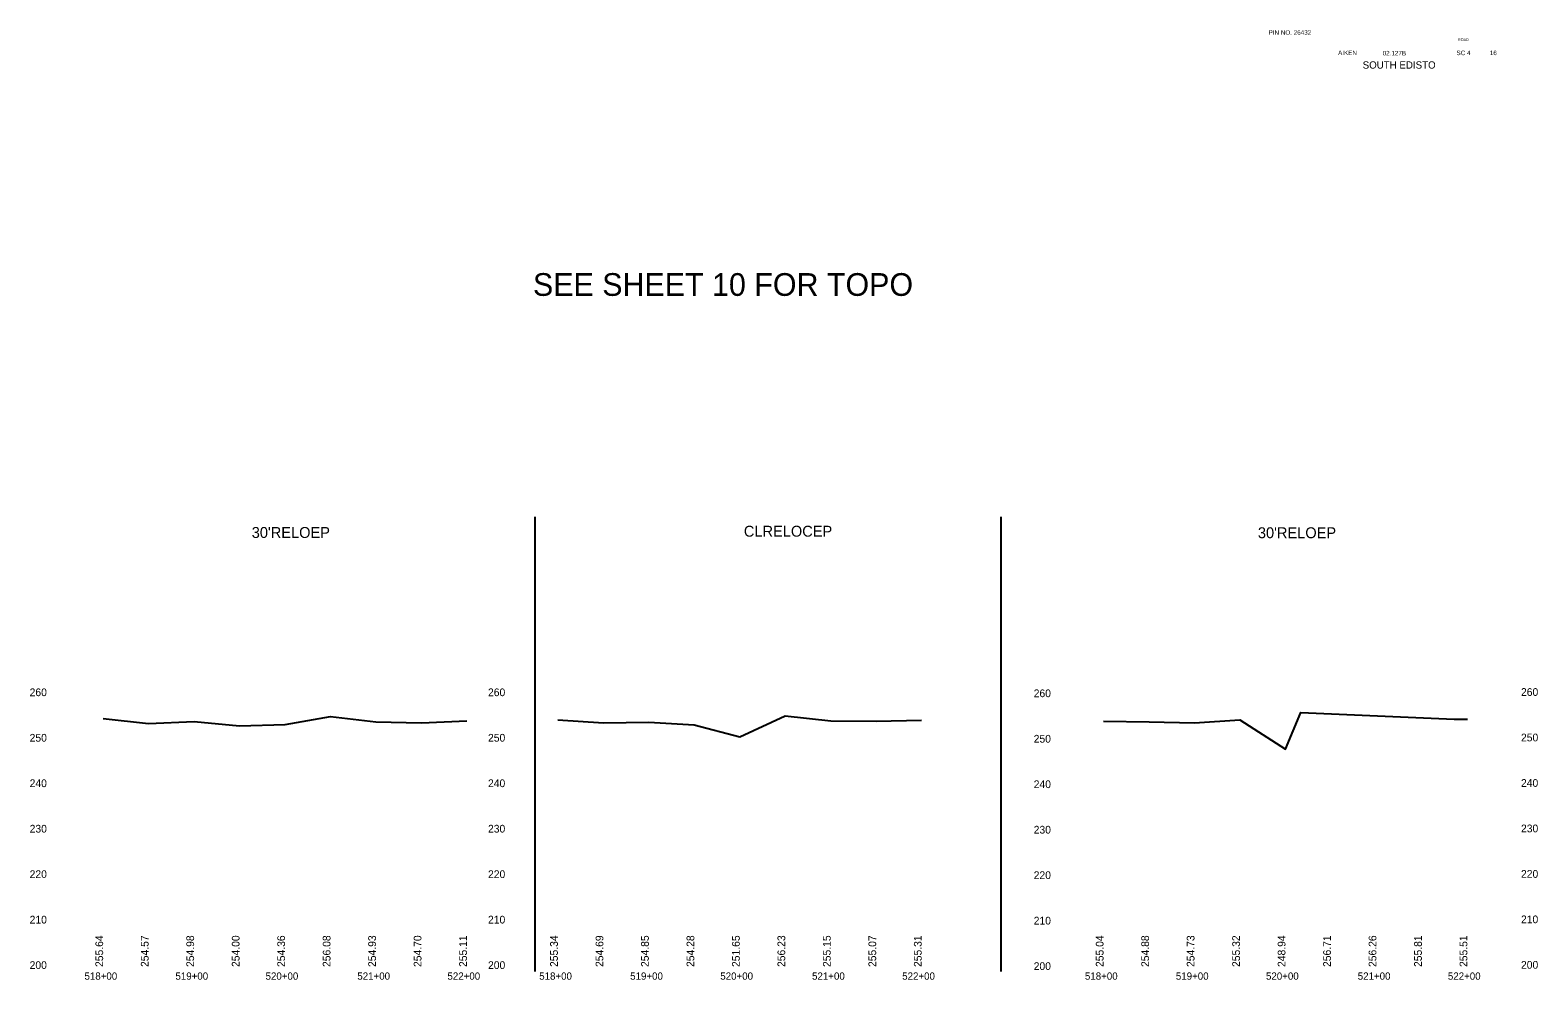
# Model space of a CAD drawing. Extents: x 49241 to 62599, y 49216 to 56011.
# Drawn here: x 50163 to 51821, y 54966 to 56011 of the extents above; entities that cross this region are included whole.
import ezdxf

# ---------------------------------------------------------------- set-up
doc = ezdxf.new("R2010")
doc.units = 0
for name, color, linetype in [('Level 1', 7, 'Continuous'), ('Level 25', 7, 'Continuous'), ('Level 40', 7, 'Continuous'), ('Level 42', 7, 'Continuous'), ('Level 43', 7, 'Continuous')]:
    doc.layers.add(name, color=color, linetype=linetype)

msp = doc.modelspace()

# ---------------------------------------------------------------- linework, layer by layer
at = {"layer": 'Level 1'}
for p, q in [((50718.5, 54975.3), (50718.5, 55475.3)), ((51231.1, 54975.3), (51231.1, 55475.3))]:
    msp.add_line(p, q, dxfattribs=at)
at = {"layer": 'Level 40'}
for points in [[(50243.5, 55253.5), (50293.5, 55248.1), (50343.5, 55250.2), (50393.5, 55245.3), (50443.5, 55247.1), (50493.5, 55255.6), (50543.5, 55249.9), (50593.5, 55248.8), (50643.5, 55250.8)], [(50743.5, 55252), (50793.5, 55248.7), (50843.5, 55249.5), (50893.5, 55246.7), (50943.5, 55233.5), (50993.5, 55256.4), (51043.5, 55251), (51093.5, 55250.6), (51143.5, 55251.8)], [(51343.5, 55250.5), (51393.5, 55249.7), (51443.5, 55248.9), (51493.5, 55251.9), (51543.5, 55220), (51560.5, 55260.3), (51729.2, 55252.7), (51743.5, 55252.8)]]:
    msp.add_lwpolyline(points, dxfattribs=at)

# ---------------------------------------------------------------- texts
at = {"layer": 'Level 1'}
for s, height, p in [('PIN NO. 26432', 5, (51525, 56005.4)), ('ROAD', 3, (51733.2, 55998.5)), ('AIKEN', 5, (51601.4, 55983.1)), ('02.127B', 5, (51650.4, 55982.7)), ('SC 4', 5, (51731.6, 55983)), ('16', 5, (51768.2, 55983)), ('SOUTH EDISTO', 8, (51628.4, 55968.2))]:
    msp.add_text(s, height=height, dxfattribs=at).set_placement(p)
at = {"layer": 'Level 25'}
msp.add_text('SEE SHEET 10 FOR TOPO', height=25, dxfattribs=at).set_placement((50716.1, 55718.3))
at = {"layer": 'Level 42'}
for s, height, p in [('260', 8.5, (50162.7, 55278.1)), ('260', 8.5, (50666.7, 55278.1)), ('260', 8.5, (51802.5, 55278.4)), ('260', 8.5, (51266.7, 55277)), ('250', 8.5, (50162.7, 55228.1)), ('250', 8.5, (50666.7, 55228.1)), ('250', 8.5, (51802.5, 55228.4)), ('250', 8.5, (51266.7, 55227)), ('240', 8.5, (51802.5, 55178.4)), ('240', 8.5, (50162.7, 55178.1)), ('240', 8.5, (50666.7, 55178.1)), ('240', 8.5, (51266.7, 55177)), ('230', 8.5, (50162.7, 55128.1)), ('230', 8.5, (50666.7, 55128.1)), ('230', 8.5, (51266.7, 55127)), ('230', 8.5, (51802.5, 55128.4)), ('220', 8.5, (50162.7, 55078.1)), ('220', 8.5, (50666.7, 55078.1)), ('220', 8.5, (51266.7, 55077)), ('220', 8.5, (51802.5, 55078.4)), ('210', 8.5, (50162.7, 55028.1)), ('210', 8.5, (50666.7, 55028.1)), ('210', 8.5, (51266.7, 55027)), ('210', 8.5, (51802.5, 55028.4)), ('200', 8.5, (50162.7, 54978.1)), ('518+00', 8, (50223, 54966.3)), ('519+00', 8, (50323, 54966.3)), ('520+00', 8, (50422.1, 54966.3)), ('521+00', 8, (50523, 54966.3)), ('522+00', 8, (50622.1, 54966.3)), ('200', 8.5, (50666.7, 54978.1)), ('518+00', 8, (50723, 54966.3)), ('519+00', 8, (50823, 54966.3)), ('520+00', 8, (50922.1, 54966.3)), ('521+00', 8, (51023, 54966.3)), ('522+00', 8, (51122.1, 54966.3)), ('200', 8.5, (51266.7, 54977)), ('518+00', 8, (51323, 54966.3)), ('519+00', 8, (51423, 54966.3)), ('520+00', 8, (51522.1, 54966.3)), ('521+00', 8, (51623, 54966.3)), ('522+00', 8, (51722.1, 54966.3)), ('200', 8.5, (51802.5, 54978.4))]:
    msp.add_text(s, height=height, dxfattribs=at).set_placement(p)
at = {"layer": 'Level 43'}
for s, p in [("30'RELOEP", (50406.9, 55452.1)), ('CLRELOCEP', (50948, 55453.5)), ("30'RELOEP", (51513.2, 55451.8))]:
    msp.add_text(s, height=12, dxfattribs=at).set_placement(p)
for s, p in [('255.64', (50243.5, 54980.3)), ('254.57', (50293.5, 54980.3)), ('254.98', (50343.5, 54980.3)), ('254.00', (50393.5, 54980.3)), ('254.36', (50443.5, 54980.3)), ('256.08', (50493.5, 54980.3)), ('254.93', (50543.5, 54980.3)), ('254.70', (50593.5, 54980.3)), ('255.11', (50643.5, 54980.3)), ('255.34', (50743.5, 54980.3)), ('254.69', (50793.5, 54980.3)), ('254.85', (50843.5, 54980.3)), ('254.28', (50893.5, 54980.3)), ('251.65', (50943.5, 54980.3)), ('256.23', (50993.5, 54980.3)), ('255.15', (51043.5, 54980.3)), ('255.07', (51093.5, 54980.3)), ('255.31', (51143.5, 54980.3)), ('255.04', (51343.5, 54980.3)), ('254.88', (51393.5, 54980.3)), ('254.73', (51443.5, 54980.3)), ('255.32', (51493.5, 54980.3)), ('248.94', (51543.5, 54980.3)), ('256.71', (51593.5, 54980.3)), ('256.26', (51643.5, 54980.3)), ('255.81', (51693.5, 54980.3)), ('255.51', (51743.5, 54980.3))]:
    msp.add_text(s, height=8.5, rotation=90, dxfattribs=at).set_placement(p)

doc.saveas('drawing.dxf')
